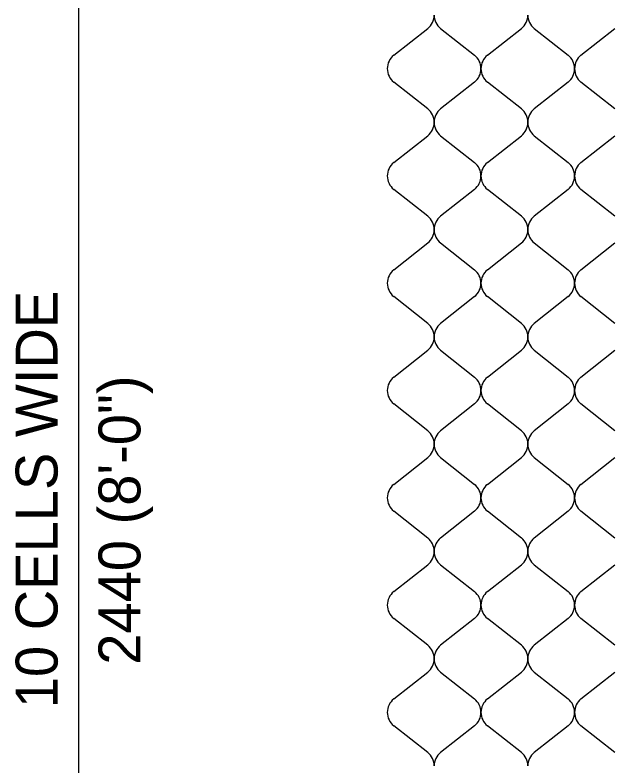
# Model space of a CAD drawing. Extents: x 638850 to 644908, y 297188 to 298900.
# Drawn here: x 640711.8 to 640754.7, y 298134.3 to 298188 of the extents above; entities that cross this region are included whole.
import ezdxf

# ---------------------------------------------------------------- set-up
doc = ezdxf.new("R2010")
doc.units = 0
for name, color, linetype in [('2', 7, 'Continuous'), ('4', 7, 'Continuous'), ('7', 7, 'Continuous')]:
    doc.layers.add(name, color=color, linetype=linetype)

msp = doc.modelspace()

# ---------------------------------------------------------------- linework, layer by layer
at = {"layer": '2'}
for p, q in [((640738.862, 298185.115), (640741.295, 298187.034)), ((640742.212, 298187.034), (640744.644, 298185.115)), ((640745.563, 298185.115), (640747.995, 298187.034)), ((640748.913, 298187.034), (640751.345, 298185.115)), ((640752.259, 298185.115), (640754.691, 298187.034)), ((640741.295, 298181.277), (640738.862, 298183.195)), ((640744.644, 298183.195), (640742.212, 298181.277)), ((640747.995, 298181.277), (640745.563, 298183.195)), ((640751.345, 298183.195), (640748.913, 298181.277)), ((640754.691, 298181.277), (640752.259, 298183.195)), ((640738.862, 298177.438), (640741.295, 298179.357)), ((640742.212, 298179.357), (640744.644, 298177.438)), ((640745.563, 298177.438), (640747.995, 298179.357)), ((640748.913, 298179.357), (640751.345, 298177.438)), ((640752.259, 298177.438), (640754.691, 298179.357)), ((640741.295, 298173.6), (640738.862, 298175.518)), ((640744.644, 298175.518), (640742.212, 298173.6)), ((640747.995, 298173.6), (640745.563, 298175.518)), ((640751.345, 298175.518), (640748.913, 298173.6)), ((640754.691, 298173.6), (640752.259, 298175.518)), ((640738.862, 298169.761), (640741.295, 298171.68)), ((640742.212, 298171.68), (640744.644, 298169.761)), ((640745.563, 298169.761), (640747.995, 298171.68)), ((640748.913, 298171.68), (640751.345, 298169.761)), ((640752.259, 298169.761), (640754.691, 298171.68)), ((640741.295, 298165.923), (640738.862, 298167.841)), ((640744.644, 298167.841), (640742.212, 298165.923)), ((640747.995, 298165.923), (640745.563, 298167.841)), ((640751.345, 298167.841), (640748.913, 298165.923)), ((640754.691, 298165.923), (640752.259, 298167.841)), ((640738.862, 298162.084), (640741.295, 298164.003)), ((640742.212, 298164.003), (640744.644, 298162.084)), ((640745.563, 298162.084), (640747.995, 298164.003)), ((640748.913, 298164.003), (640751.345, 298162.084)), ((640752.259, 298162.084), (640754.691, 298164.003)), ((640741.295, 298158.246), (640738.862, 298160.164)), ((640744.644, 298160.164), (640742.212, 298158.246)), ((640747.995, 298158.246), (640745.563, 298160.164)), ((640751.345, 298160.164), (640748.913, 298158.246)), ((640754.691, 298158.246), (640752.259, 298160.164)), ((640738.862, 298154.407), (640741.295, 298156.326)), ((640742.212, 298156.326), (640744.644, 298154.407)), ((640745.563, 298154.407), (640747.995, 298156.326)), ((640748.913, 298156.326), (640751.345, 298154.407)), ((640752.259, 298154.407), (640754.691, 298156.326)), ((640741.295, 298150.569), (640738.862, 298152.487)), ((640744.644, 298152.487), (640742.212, 298150.569)), ((640747.995, 298150.569), (640745.563, 298152.487)), ((640751.345, 298152.487), (640748.913, 298150.569)), ((640754.691, 298150.569), (640752.259, 298152.487)), ((640738.862, 298146.73), (640741.295, 298148.649)), ((640742.212, 298148.649), (640744.644, 298146.73)), ((640745.563, 298146.73), (640747.995, 298148.649)), ((640748.913, 298148.649), (640751.345, 298146.73)), ((640752.259, 298146.73), (640754.691, 298148.649)), ((640741.295, 298142.892), (640738.862, 298144.81)), ((640744.644, 298144.81), (640742.212, 298142.892)), ((640747.995, 298142.892), (640745.563, 298144.81)), ((640751.345, 298144.81), (640748.913, 298142.892)), ((640754.691, 298142.892), (640752.259, 298144.81)), ((640738.862, 298139.053), (640741.295, 298140.972)), ((640742.212, 298140.972), (640744.644, 298139.053)), ((640745.563, 298139.053), (640747.995, 298140.972)), ((640748.913, 298140.972), (640751.345, 298139.053)), ((640752.259, 298139.053), (640754.691, 298140.972)), ((640741.295, 298135.215), (640738.862, 298137.133)), ((640744.644, 298137.133), (640742.212, 298135.215)), ((640747.995, 298135.215), (640745.563, 298137.133)), ((640751.345, 298137.133), (640748.913, 298135.215)), ((640754.691, 298135.215), (640752.259, 298137.133))]:
    msp.add_line(p, q, dxfattribs=at)
for centre, start, end in [((640740.519, 298187.994), 308.9482, 0), ((640742.988, 298187.994), 180, 231.0518), ((640747.219, 298187.994), 308.9482, 0), ((640749.689, 298187.994), 180, 231.0518), ((640739.639, 298184.155), 128.9482, 180), ((640743.868, 298184.155), 0, 51.0518), ((640746.34, 298184.155), 128.9482, 180), ((640750.568, 298184.155), 0, 51.0518), ((640753.036, 298184.155), 128.9482, 180), ((640739.639, 298184.155), 180, 231.0518), ((640743.868, 298184.155), 308.9482, 0), ((640746.34, 298184.155), 180, 231.0518), ((640750.568, 298184.155), 308.9482, 0), ((640753.036, 298184.155), 180, 231.0518), ((640740.519, 298180.317), 0, 51.0518), ((640742.988, 298180.317), 128.9482, 180), ((640747.219, 298180.317), 0, 51.0518), ((640749.689, 298180.317), 128.9482, 180), ((640740.519, 298180.317), 308.9482, 0), ((640742.988, 298180.317), 180, 231.0518), ((640747.219, 298180.317), 308.9482, 0), ((640749.689, 298180.317), 180, 231.0518), ((640739.639, 298176.478), 128.9482, 180), ((640743.868, 298176.478), 0, 51.0518), ((640746.34, 298176.478), 128.9482, 180), ((640750.568, 298176.478), 0, 51.0518), ((640753.036, 298176.478), 128.9482, 180), ((640739.639, 298176.478), 180, 231.0518), ((640743.868, 298176.478), 308.9482, 0), ((640746.34, 298176.478), 180, 231.0518), ((640750.568, 298176.478), 308.9482, 0), ((640753.036, 298176.478), 180, 231.0518), ((640740.519, 298172.64), 0, 51.0518), ((640742.988, 298172.64), 128.9482, 180), ((640747.219, 298172.64), 0, 51.0518), ((640749.689, 298172.64), 128.9482, 180), ((640740.519, 298172.64), 308.9482, 0), ((640742.988, 298172.64), 180, 231.0518), ((640747.219, 298172.64), 308.9482, 0), ((640749.689, 298172.64), 180, 231.0518), ((640739.639, 298168.801), 128.9482, 180), ((640743.868, 298168.801), 0, 51.0518), ((640746.34, 298168.801), 128.9482, 180), ((640750.568, 298168.801), 0, 51.0518), ((640753.036, 298168.801), 128.9482, 180), ((640739.639, 298168.801), 180, 231.0518), ((640743.868, 298168.801), 308.9482, 0), ((640746.34, 298168.801), 180, 231.0518), ((640750.568, 298168.801), 308.9482, 0), ((640753.036, 298168.801), 180, 231.0518), ((640740.519, 298164.963), 0, 51.0518), ((640742.988, 298164.963), 128.9482, 180), ((640747.219, 298164.963), 0, 51.0518), ((640749.689, 298164.963), 128.9482, 180), ((640740.519, 298164.963), 308.9482, 0), ((640742.988, 298164.963), 180, 231.0518), ((640747.219, 298164.963), 308.9482, 0), ((640749.689, 298164.963), 180, 231.0518), ((640739.639, 298161.124), 128.9482, 180), ((640743.868, 298161.124), 0, 51.0518), ((640746.34, 298161.124), 128.9482, 180), ((640750.568, 298161.124), 0, 51.0518), ((640753.036, 298161.124), 128.9482, 180), ((640739.639, 298161.124), 180, 231.0518), ((640743.868, 298161.124), 308.9482, 0), ((640746.34, 298161.124), 180, 231.0518), ((640750.568, 298161.124), 308.9482, 0), ((640753.036, 298161.124), 180, 231.0518), ((640740.519, 298157.286), 0, 51.0518), ((640742.988, 298157.286), 128.9482, 180), ((640747.219, 298157.286), 0, 51.0518), ((640749.689, 298157.286), 128.9482, 180), ((640740.519, 298157.286), 308.9482, 0), ((640742.988, 298157.286), 180, 231.0518), ((640747.219, 298157.286), 308.9482, 0), ((640749.689, 298157.286), 180, 231.0518), ((640739.639, 298153.447), 128.9482, 180), ((640743.868, 298153.447), 0, 51.0518), ((640746.34, 298153.447), 128.9482, 180), ((640750.568, 298153.447), 0, 51.0518), ((640753.036, 298153.447), 128.9482, 180), ((640739.639, 298153.447), 180, 231.0518), ((640743.868, 298153.447), 308.9482, 0), ((640746.34, 298153.447), 180, 231.0518), ((640750.568, 298153.447), 308.9482, 0), ((640753.036, 298153.447), 180, 231.0518), ((640740.519, 298149.609), 0, 51.0518), ((640742.988, 298149.609), 128.9482, 180), ((640747.219, 298149.609), 0, 51.0518), ((640749.689, 298149.609), 128.9482, 180), ((640740.519, 298149.609), 308.9482, 0), ((640742.988, 298149.609), 180, 231.0518), ((640747.219, 298149.609), 308.9482, 0), ((640749.689, 298149.609), 180, 231.0518), ((640739.639, 298145.77), 128.9482, 180), ((640743.868, 298145.77), 0, 51.0518), ((640746.34, 298145.77), 128.9482, 180), ((640750.568, 298145.77), 0, 51.0518), ((640753.036, 298145.77), 128.9482, 180), ((640739.639, 298145.77), 180, 231.0518), ((640743.868, 298145.77), 308.9482, 0), ((640746.34, 298145.77), 180, 231.0518), ((640750.568, 298145.77), 308.9482, 0), ((640753.036, 298145.77), 180, 231.0518), ((640740.519, 298141.932), 0, 51.0518), ((640742.988, 298141.932), 128.9482, 180), ((640747.219, 298141.932), 0, 51.0518), ((640749.689, 298141.932), 128.9482, 180), ((640740.519, 298141.932), 308.9482, 0), ((640742.988, 298141.932), 180, 231.0518), ((640747.219, 298141.932), 308.9482, 0), ((640749.689, 298141.932), 180, 231.0518), ((640739.639, 298138.093), 128.9482, 180), ((640743.868, 298138.093), 0, 51.0518), ((640746.34, 298138.093), 128.9482, 180), ((640750.568, 298138.093), 0, 51.0518), ((640753.036, 298138.093), 128.9482, 180), ((640739.639, 298138.093), 180, 231.0518), ((640743.868, 298138.093), 308.9482, 0), ((640746.34, 298138.093), 180, 231.0518), ((640750.568, 298138.093), 308.9482, 0), ((640753.036, 298138.093), 180, 231.0518), ((640740.519, 298134.255), 0, 51.0518), ((640742.988, 298134.255), 128.9482, 180), ((640747.219, 298134.255), 0, 51.0518), ((640749.689, 298134.255), 128.9482, 180)]:
    msp.add_arc(centre, 1.235, start, end, dxfattribs=at)
at = {"layer": '7'}
msp.add_line((640716.302, 298195.671), (640716.302, 298118.456), dxfattribs=at)

# ---------------------------------------------------------------- texts
at = {"layer": '4'}
for s, p in [('10 CELLS WIDE', (640714.811, 298138.388)), ('2440 (8\'-0")', (640720.738, 298141.502))]:
    msp.add_text(s, height=3, rotation=90, dxfattribs=at).set_placement(p)

doc.saveas('drawing.dxf')
